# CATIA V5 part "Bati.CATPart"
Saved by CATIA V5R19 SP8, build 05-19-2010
Part number: Bati
Bounding box of the stored display mesh (mm): x -353.836 to 1349.047, y -196.441 to 270, z 0 to 500
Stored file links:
  C:\Users\ThinkMotion\Desktop\EU_thinkMotion\iao\IAO_MMS_Groupe3\yschmidt\Train1434_yschmidt\Train1434_yschmidt\Bati.CATPart
  C:\Users\ThinkMotion\Desktop\EU_thinkMotion\iao\IAO_MMS_Groupe3\yschmidt\Train1434_yschmidt\Train1434_yschmidt\AssemblageTrainOptimise.CATProduct
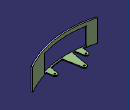
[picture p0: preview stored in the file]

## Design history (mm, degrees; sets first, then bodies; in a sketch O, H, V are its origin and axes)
Set1
  Line1 to Line3: linked copy from another document
Set2
  Point1: (0, 0, 0)
  Point2: (255, 220, 0)
  Point3: (750, 50, 0)
Body1 (main body)
  Sketch1 on xy-plane, origin (0, 0, 0), H (1, 0, 0), V (0, 1, 0)
    spline S1 through (-353.8359, -86.2792) (234.3932, -166.7461) (1349.0471, 141.9576)
    spline S2 through (-353.8359, -116.2792) (343.9911, -193.6674) (1349.0471, 111.9576)
    line L1 (1349.0471, 141.9576) -> (1349.0471, 111.9576)
    point P1 (1349.0471, 141.9576)
    point P2 (1349.0471, 111.9576)
    line L2 (-353.8359, -86.2792) -> (-353.8359, -116.2792)
    point P3 (-353.8359, -116.2792)
    point P4 (-353.8359, -86.2792)
    reference projected point E1 (0, 0) from Point1
    reference projected point E2 (0, 0) from Point1
    point P5 (1349.0471, 141.9576)
    point P6 (1349.0471, 111.9576)
    point P7 (-353.8359, -116.2792)
    point P8 (-353.8359, -86.2792)
    distance S1 S2 = 30
    length L1 = 30
    length L2 = 30
    distance P4 E1 = 364.2032
    distance E2 P1 = 1356.4955
    coincidence: P5 P1, P6 P2, P7 P3, P4 S1, P8 P4
    vertical: L1 V, L2 V
  Pad1: profile Sketch1, direction (0, 0, 1), length 500
  Sketch2 on xy-plane, origin (0, 0, 0), H (1, 0, 0), V (0, 1, 0)
    arc A1 centre (0, 0) radius 50 from (49.2404, 8.6824) to (-49.2404, 8.6824) ccw
    line L1 (-49.2404, 8.6824) -> (-76.208, -144.2584)
    point P1 (-76.208, -144.2584)
    point P2 (-49.2404, 8.6824)
    point P3 (-49.2404, 8.6824)
    reference projected curve E1 from edge [face of Pad1 from Sketch1.S1 | end face of Pad1]
    line L2 (49.2404, 8.6824) -> (79.1918, -161.1802)
    point P5 (79.1918, -161.1802)
    reference projected curve E2 from edge [face of Pad1 from Sketch1.S1 | end face of Pad1]
    circle A2 centre (0, 0) radius 15
    point P6 (0, 0)
    arc A3 centre (255, 220) radius 50 from (304.2404, 228.6824) to (205.7596, 228.6824) ccw
    reference projected point E3 (255, 220) from Point2
    line L3 (205.7596, 228.6824) -> (136.4204, -164.5598)
    point P9 (136.4204, -164.5598)
    line L4 (304.2404, 228.6824) -> (373.1273, -161.9949)
    point P11 (373.1273, -161.9949)
    construction line L5 (255, 220) -> (255, -256.9652)
    reference projected curve E4 from edge [face of Pad1 from Sketch1.S1 | end face of Pad1]
    reference projected curve E5 from edge [face of Pad1 from Sketch1.S1 | end face of Pad1]
    circle A4 centre (255, 220) radius 15
    point P13 (255, 220)
    arc A5 centre (750, 50) radius 50 from (799.2404, 58.6824) to (700.7596, 58.6824) ccw
    point P14 (750, 50)
    reference projected point E6 (750, 50) from Point3
    line L6 (799.2404, 58.6824) -> (823.9763, -81.6017)
    point P16 (823.9763, -81.6017)
    line L7 (700.7596, 58.6824) -> (669.1529, -120.5682)
    point P18 (669.1529, -120.5682)
    reference projected curve E7 from edge [face of Pad1 from Sketch1.S1 | end face of Pad1]
    reference projected curve E8 from edge [face of Pad1 from Sketch1.S1 | end face of Pad1]
    axis line L8 (750, 50) -> (750, -160.7654)
    circle A6 centre (750, 50) radius 15
    reference projected point E9 (255, 220) from Point2
    reference projected point E10 (0, 0) from Point1
    spline S1 through (-76.208, -144.2584) (-8.3016, -170.1815) (79.1918, -161.1802)
    spline S2 through (136.4204, -164.5598) (255, -186.5793) (373.1273, -161.9949)
    spline S3 through (669.1529, -120.5682) (764.7796, -111.4665) (823.9763, -81.6017)
    reference projected point E11 (0, 0) from Line1
    reference projected point E12 (255, 220) from Line2
    reference projected point E13 (750, 50) from Line3
    point P20 (-76.208, -144.2584)
    point P21 (79.1918, -161.1802)
    point P22 (136.4204, -164.5598)
    point P23 (255, -186.5793)
    point P24 (373.1273, -161.9949)
    point P25 (669.1529, -120.5682)
    point P26 (823.9763, -81.6017)
    angle L2 V = 10
    angle L1 V = 10
    radius A2 = 15
    radius A1 = 50
    angle L3 L5 = 10
    angle L5 L4 = 10
    radius A3 = 50
    radius A4 = 15
    angle L8 L6 = 10
    angle L7 L8 = 10
    radius A5 = 50
    radius A6 = 15
    coincidence: E1 P1, P5 E2, P3 P2, P9 E4, P11 E5, P14 E6, P16 E7, P18 E8, P13 E9, P6 E10, P20 P1, P21 P5, P22 P9, P23 L5, P24 P11, P25 P18, P26 P16
    tangency: L2 A1, L1 A1, A3 L3, A3 L4, L6 A5, A5 L7
    concentricity: E3 A3, E11 A2, E12 A4, E13 A6
    vertical: L5 V, L8 V
  Pad2: profile Sketch2, direction (0, 0, 1), length 19
  Sketch3 on zx-plane, origin (0, 0, 0), H (-1, 0, 0), V (0, 0, 1)
    line L1 (153.8359, 19) -> (-863.733, 19)
    line L2 (-863.733, 19) -> (-863.733, 419)
    line L3 (-863.733, 419) -> (153.8359, 419)
    line L4 (153.8359, 419) -> (153.8359, 19)
    reference projected line E1 (49.2404, 19) -> (71.5164, 19) from edge [face of Pad2 from Sketch2.L1 | end face of Pad2]
    reference projected line E2 (353.8359, 0) -> (353.8359, 500) from edge [face of Pad1 from Sketch1.L2 | face of Pad1 from Sketch1.S1]
    distance L3 L1 = 400
    distance L4 E2 = 200
    horizontal: L1 H, L3 H
    vertical: L2 V, L4 V
    coincidence: L1 E1
  Pocket1: profile Sketch3, direction (0, -1, 0), length 500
